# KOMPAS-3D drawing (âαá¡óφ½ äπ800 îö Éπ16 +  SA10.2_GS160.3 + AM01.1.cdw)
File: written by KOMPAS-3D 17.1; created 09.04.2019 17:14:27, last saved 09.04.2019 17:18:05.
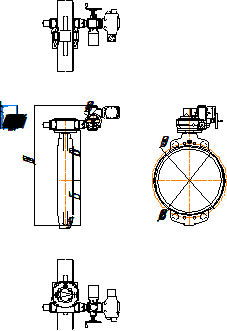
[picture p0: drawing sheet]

Sheet 1: A4, portrait

Title block, sheet 1: name: Гранвэл Ду800 МФ Ру16 + / SA10.2_GS160.3 + AM01.1; material: Внимание! Данный продукт является объектом авторского права ООО «Торговый Дом АДЛ». / Запрещается изменение, копирование, распространение / (в том числе путем копирования на другие сайты и ресурсы в Интернете) / или любое иное использование информации и объектов без предварительного / согласия правообладателя (ООО «Торговый Дом АДЛ»).; mass: 946,39; sheets: 1; organisation: ООО "Торговый дом АДЛ"; sheet format: A4

Views: Вид 1, Спереди, Проекционный вид 2, Проекционный вид 3
Referenced files in \\adlc.lan\data\АДЛ_ПКД\3D-модели\ADL production\Дисковые поворотные затворы ГРАНВЭЛ\межфланцевый с эл.приводом Auma Ру 16\KOMPAS 3D\: Гранвэл Ду800 МФ Ру16 + SA10.2_GS160.3 + AM01.1.m3d
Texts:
  user
Dimensions and other numbers on the sheet: 630; 565; 135; 1517,8; 200; 1:1; 1; 946,39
